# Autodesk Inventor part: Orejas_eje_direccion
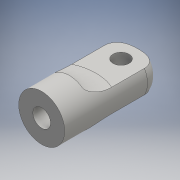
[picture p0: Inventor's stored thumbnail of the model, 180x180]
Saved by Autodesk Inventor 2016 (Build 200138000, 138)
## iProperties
Created: 2017-06
Part Number: Orejas_eje_direccion
Material: Generic
Document SubType Name: Modeling
Designer: laboratorioesan
Density: 1 g/cm^3
Appearance: Default
Author: laboratorioesan
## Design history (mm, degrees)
sketch "Sketch1"
  geometry: C1 r 3.85 at (0, 0); C2 r 10 at (0, 0); 1 further point
  constraints: 2 centre point, 2 coincident
  dimensions: "d0" = 7.7 diameter of C1; "d1" = 20 diameter of C2
extrude "Extrusion1" new body sketch "Sketch1" distance "d2" = 12; taper "d3" = 0 deg
sketch "Sketch2"
  geometry: C1 r 3.85 at (0, 0) reference; C2 r 10 at (0, 0) reference; 1 further point
extrude "Extrusion2" join sketch "Sketch2" distance "d4" = 30; taper "d5" = 0 deg
sketch "Sketch3"
  geometry: L1 (-8.66, 5)-(8.66, 5); L2 (8.66, -5)-(-8.66, -5); C1 r 10 at (0, 0) reference; A1 r 10 centre (0, 0) between (-8.66, 5) and (-8.66, -5); A2 r 10 centre (0, 0) between (8.66, -5) and (8.66, 5); 2 further points
  constraints: 4 end point, 4 point on circle, 2 centre point, 1 coincident, 1 horizontal, 1 midpoint, 1 parallel, 1 vertical alignment
  dimensions: "d8" = 20 diameter of C1 (derived); "d9" = 10 distance between parallel lines of L2 L1
extrude "Extrusion3" cut sketch "Sketch3" distance "d10" = 30; taper "d11" = 0 deg
sketch "Sketch4"
  geometry: L1 (0, 0)-(17.321, 0) reference; L2 (0, -30)-(0, 0) reference; L3 (0, -30)-(17.321, -30) reference; L4 (17.321, 0)-(17.321, -30) reference; C1 r 3.5 at (8.66, -7.5); 1 further point
  constraints: 1 centre point
  dimensions: "d12" = 7 diameter of C1; "d13" = 7.5 distance from line of L1 C1.centre
extrude "Extrusion4" cut sketch "Sketch4" distance "d14" = 15; taper "d15" = 0 deg
fillet "Fillet1" dims "d16" = 16
fillet "Fillet2" dims "d17" = 16
fillet "Fillet3" dims "d18" = 6
fillet "Fillet4" dims "d19" = 3.5
body "Solid1"
node "Projected Loop1"
node "Projected Loop2"
node "Projected Loop3"
